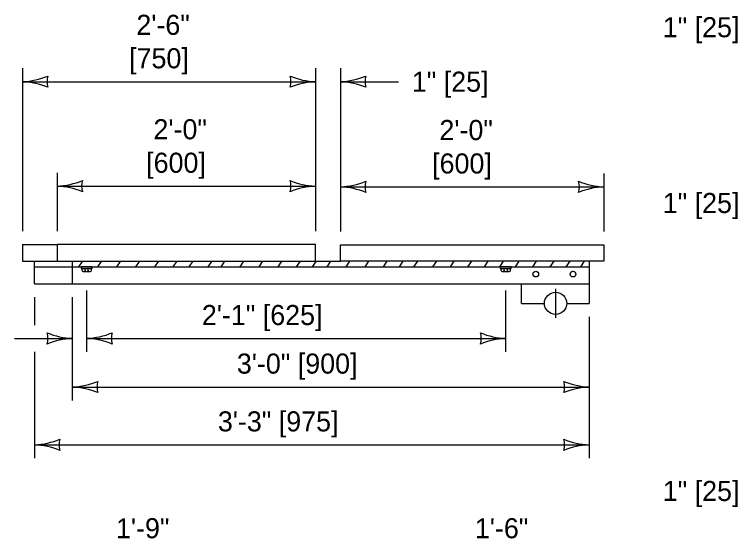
# Model space of a CAD drawing. Extents: x 49991.4 to 50021, y 49987.6 to 50011.4.
# Drawn here: x 50003.358 to 50005.519, y 49990.946 to 49992.512 of the extents above; entities that cross this region are included whole.
import ezdxf

# ---------------------------------------------------------------- set-up
doc = ezdxf.new("R2010")
doc.units = 0
for name, color, linetype in [('Level 1', 7, 'Continuous'), ('Level 2', 7, 'Continuous'), ('Level 3', 7, 'Continuous'), ('Level 4', 7, 'Continuous'), ('Level 5', 7, 'Continuous')]:
    doc.layers.add(name, color=color, linetype=linetype)

msp = doc.modelspace()

# ---------------------------------------------------------------- linework, layer by layer
at = {"layer": 'Level 1'}
for p, q in [((50003.485, 49991.8246), (50003.485, 49991.7746)), ((50004.2575, 49991.8246), (50003.485, 49991.8246)), ((50004.2575, 49991.7746), (50004.2575, 49991.8246)), ((50004.3321, 49991.8236), (50005.1198, 49991.8236)), ((50004.3321, 49991.7746), (50004.3321, 49991.8236)), ((50005.1198, 49991.8241), (50005.1198, 49991.7751)), ((50003.485, 49991.7746), (50004.2575, 49991.7746)), ((50003.5311, 49991.7076), (50003.5311, 49991.7746)), ((50003.5497, 49991.7579), (50003.5606, 49991.774)), ((50003.6065, 49991.7579), (50003.6174, 49991.774)), ((50003.6634, 49991.7579), (50003.6743, 49991.774)), ((50003.7203, 49991.7579), (50003.7312, 49991.774)), ((50003.7771, 49991.7579), (50003.788, 49991.774)), ((50003.8323, 49991.7583), (50003.8432, 49991.7744)), ((50003.8801, 49991.7579), (50003.891, 49991.774)), ((50003.937, 49991.7579), (50003.9479, 49991.774)), ((50003.9754, 49991.7579), (50003.9866, 49991.7746)), ((50004.0322, 49991.7579), (50004.0435, 49991.7746)), ((50004.0891, 49991.7579), (50004.1004, 49991.7746)), ((50004.1459, 49991.7579), (50004.1572, 49991.7746)), ((50004.2008, 49991.7579), (50004.2122, 49991.7746)), ((50004.2489, 49991.7579), (50004.2602, 49991.7746)), ((50004.2575, 49991.7746), (50004.3321, 49991.7746)), ((50004.292, 49991.7579), (50004.3033, 49991.7746)), ((50005.1198, 49991.7746), (50004.3321, 49991.7746)), ((50004.3489, 49991.7579), (50004.3602, 49991.7746)), ((50004.4057, 49991.7579), (50004.417, 49991.7746)), ((50004.4606, 49991.7579), (50004.472, 49991.7746)), ((50004.5087, 49991.7579), (50004.52, 49991.7746)), ((50004.5518, 49991.7579), (50004.563, 49991.7746)), ((50004.6087, 49991.7579), (50004.6199, 49991.7746)), ((50004.661, 49991.7579), (50004.6722, 49991.7746)), ((50004.7133, 49991.7579), (50004.7245, 49991.7746)), ((50004.7628, 49991.7579), (50004.774, 49991.7746)), ((50004.8083, 49991.7579), (50004.8196, 49991.7746)), ((50004.8552, 49991.7579), (50004.8665, 49991.7746)), ((50004.9073, 49991.7579), (50004.9185, 49991.7746)), ((50004.9591, 49991.7579), (50004.9704, 49991.7746)), ((50005.0071, 49991.7579), (50005.0184, 49991.7746)), ((50005.0502, 49991.7579), (50005.0616, 49991.7748)), ((50005.0755, 49991.7746), (50005.0755, 49991.649)), ((50003.5319, 49991.7579), (50005.0755, 49991.7579)), ((50003.56, 49991.7469), (50003.56, 49991.7532)), ((50003.5626, 49991.7443), (50003.5852, 49991.7443)), ((50003.5692, 49991.7468), (50003.5692, 49991.7532)), ((50003.5784, 49991.7468), (50003.5784, 49991.7532)), ((50003.5877, 49991.7469), (50003.5877, 49991.7532)), ((50004.8125, 49991.7469), (50004.8125, 49991.7532)), ((50004.8151, 49991.7443), (50004.8377, 49991.7443)), ((50004.8217, 49991.7468), (50004.8217, 49991.7532)), ((50004.8309, 49991.7468), (50004.8309, 49991.7532)), ((50004.8402, 49991.7469), (50004.8402, 49991.7532)), ((50003.5311, 49991.7076), (50004.8728, 49991.7076)), ((50004.8728, 49991.649), (50004.8728, 49991.7076)), ((50004.8728, 49991.7076), (50005.0755, 49991.7076)), ((50004.8728, 49991.649), (50004.9418, 49991.649)), ((50005.0083, 49991.649), (50005.0755, 49991.649))]:
    msp.add_line(p, q, dxfattribs=at)
for points in [[(50003.5573, 49991.7579), (50003.5573, 49991.7532), (50003.5901, 49991.7532), (50003.5901, 49991.7579)], [(50004.8098, 49991.7579), (50004.8098, 49991.7532), (50004.8426, 49991.7532), (50004.8426, 49991.7579)]]:
    msp.add_lwpolyline(points, close=True, dxfattribs=at)
for centre, radius in [((50004.9159, 49991.7363), 0.00843), ((50005.027, 49991.7363), 0.00843), ((50004.9751, 49991.649), 0.0333)]:
    msp.add_circle(centre, radius, dxfattribs=at)
for centre, start, end in [((50003.5626, 49991.7468), 180, 270), ((50003.5667, 49991.7468), 270, 0), ((50003.5718, 49991.7468), 180, 270), ((50003.5759, 49991.7468), 270, 0), ((50003.581, 49991.7468), 180, 270), ((50003.5851, 49991.7468), 270, 0), ((50004.8151, 49991.7468), 180, 270), ((50004.8192, 49991.7468), 270, 0), ((50004.8243, 49991.7468), 180, 270), ((50004.8284, 49991.7468), 270, 0), ((50004.8335, 49991.7468), 180, 270), ((50004.8376, 49991.7468), 270, 0)]:
    msp.add_arc(centre, 0.00257, start, end, dxfattribs=at)
at = {"layer": 'Level 3'}
for p, q in [((50003.3817, 49992.3515), (50003.3817, 49991.8646)), ((50004.2575, 49992.3515), (50004.2575, 49991.8646)), ((50004.3321, 49992.3515), (50004.3321, 49991.8636)), ((50003.3817, 49992.3115), (50004.2575, 49992.3115)), ((50004.3321, 49992.3115), (50004.5055, 49992.3115)), ((50003.485, 49992.0393), (50003.485, 49991.8646)), ((50005.1198, 49992.0371), (50005.1198, 49991.8636)), ((50003.485, 49991.9993), (50004.2575, 49991.9993)), ((50004.3321, 49991.9971), (50005.1198, 49991.9971)), ((50003.5739, 49991.5042), (50003.5739, 49991.6872)), ((50004.8264, 49991.5042), (50004.8264, 49991.6872)), ((50003.4175, 49991.6676), (50003.4175, 49991.5842)), ((50003.5311, 49991.359), (50003.5311, 49991.6676)), ((50003.5311, 49991.5781), (50003.5311, 49991.6397)), ((50005.0755, 49991.609), (50005.0755, 49991.1863)), ((50003.3577, 49991.5442), (50003.5311, 49991.5442)), ((50003.5739, 49991.5442), (50004.8264, 49991.5442)), ((50003.4175, 49991.5042), (50003.4175, 49991.1863)), ((50003.5311, 49991.399), (50005.0755, 49991.399)), ((50003.4175, 49991.2263), (50005.0755, 49991.2263))]:
    msp.add_line(p, q, dxfattribs=at)
for centre, radius, start, end in [((50003.3702, 49992.5442), 0.233, 272.8273, 292.0772), ((50003.5099, 49992.3115), 0.0548, 162.1388, 197.8612), ((50004.2667, 49992.5336), 0.2223, 247.456, 267.6395), ((50004.1293, 49992.3115), 0.0548, 342.1388, 17.8612), ((50004.3206, 49992.5442), 0.233, 272.8273, 292.0772), ((50004.4603, 49992.3115), 0.0548, 162.1388, 197.8612), ((50003.3725, 49992.0894), 0.2223, 67.456, 87.6395), ((50004.269, 49992.0788), 0.233, 92.8273, 112.0772), ((50004.3229, 49992.0894), 0.2223, 67.456, 87.6395), ((50003.4735, 49992.232), 0.233, 272.8273, 292.0772), ((50003.4758, 49991.7772), 0.2223, 67.456, 87.6395), ((50003.6132, 49991.9993), 0.0548, 162.1388, 197.8612), ((50004.2667, 49992.2214), 0.2223, 247.456, 267.6395), ((50004.1293, 49991.9993), 0.0548, 342.1388, 17.8612), ((50004.269, 49991.7666), 0.233, 92.8273, 112.0772), ((50004.3206, 49992.2298), 0.233, 272.8273, 292.0772), ((50004.4603, 49991.9971), 0.0548, 162.1388, 197.8612), ((50005.129, 49992.2192), 0.2223, 247.456, 267.6395), ((50004.9916, 49991.9971), 0.0548, 342.1388, 17.8612), ((50004.3229, 49991.775), 0.2223, 67.456, 87.6395), ((50005.1313, 49991.7644), 0.233, 92.8273, 112.0772), ((50003.5403, 49991.7663), 0.2223, 247.456, 267.6395), ((50003.4029, 49991.5442), 0.0548, 342.1388, 17.8612), ((50003.5426, 49991.3115), 0.233, 92.8273, 112.0772), ((50003.5624, 49991.7769), 0.233, 272.8273, 292.0772), ((50003.5647, 49991.3221), 0.2223, 67.456, 87.6395), ((50003.7021, 49991.5442), 0.0548, 162.1388, 197.8612), ((50004.8356, 49991.7663), 0.2223, 247.456, 267.6395), ((50004.6982, 49991.5442), 0.0548, 342.1388, 17.8612), ((50004.8379, 49991.3115), 0.233, 92.8273, 112.0772), ((50003.5196, 49991.6317), 0.233, 272.8273, 292.0772), ((50003.6593, 49991.399), 0.0548, 162.1388, 197.8612), ((50005.0847, 49991.6211), 0.2223, 247.456, 267.6395), ((50004.9473, 49991.399), 0.0548, 342.1388, 17.8612), ((50003.5219, 49991.1769), 0.2223, 67.456, 87.6395), ((50005.087, 49991.1663), 0.233, 92.8273, 112.0772), ((50003.406, 49991.459), 0.233, 272.8273, 292.0772), ((50003.5457, 49991.2263), 0.0548, 162.1388, 197.8612), ((50005.0847, 49991.4484), 0.2223, 247.456, 267.6395), ((50004.9473, 49991.2263), 0.0548, 342.1388, 17.8612), ((50003.4083, 49991.0042), 0.2223, 67.456, 87.6395), ((50005.087, 49990.9936), 0.233, 92.8273, 112.0772)]:
    msp.add_arc(centre, radius, start, end, dxfattribs=at)
at = {"layer": 'Level 4'}
for p, q in [((50003.3817, 49991.8246), (50003.485, 49991.8246)), ((50003.3817, 49991.8246), (50003.3817, 49991.7746)), ((50003.3817, 49991.7746), (50003.485, 49991.7746)), ((50003.4175, 49991.7076), (50003.4175, 49991.7746)), ((50003.4175, 49991.7579), (50003.5311, 49991.7579)), ((50003.4175, 49991.7076), (50003.5311, 49991.7076))]:
    msp.add_line(p, q, dxfattribs=at)
at = {"layer": 'Level 5'}
msp.add_line((50004.975, 49991.6923), (50004.975, 49991.6058), dxfattribs=at)

# ---------------------------------------------------------------- texts
at = {"layer": 'Level 2'}
for s, p in [('2\'-6"', (50003.7221, 49992.4515)), ('1" [25]', (50005.2955, 49992.4443)), ('[750]', (50003.7003, 49992.3515)), ('1" [25]', (50004.5455, 49992.2815)), ('2\'-0"', (50003.7732, 49992.1393)), ('2\'-0"', (50004.6279, 49992.1371)), ('[600]', (50003.7514, 49992.0393)), ('[600]', (50004.6061, 49992.0371)), ('1" [25]', (50005.2955, 49991.919)), ('2\'-1" [625]', (50003.9179, 49991.5842)), ('3\'-0" [900]', (50004.0225, 49991.439)), ('3\'-3" [975]', (50003.9657, 49991.2663)), ('1" [25]', (50005.2955, 49991.0583)), ('1\'-9"', (50003.6612, 49990.947)), ('1\'-6"', (50004.7339, 49990.947))]:
    msp.add_text(s, height=0.06, dxfattribs=at).set_placement(p)

doc.saveas('drawing.dxf')
